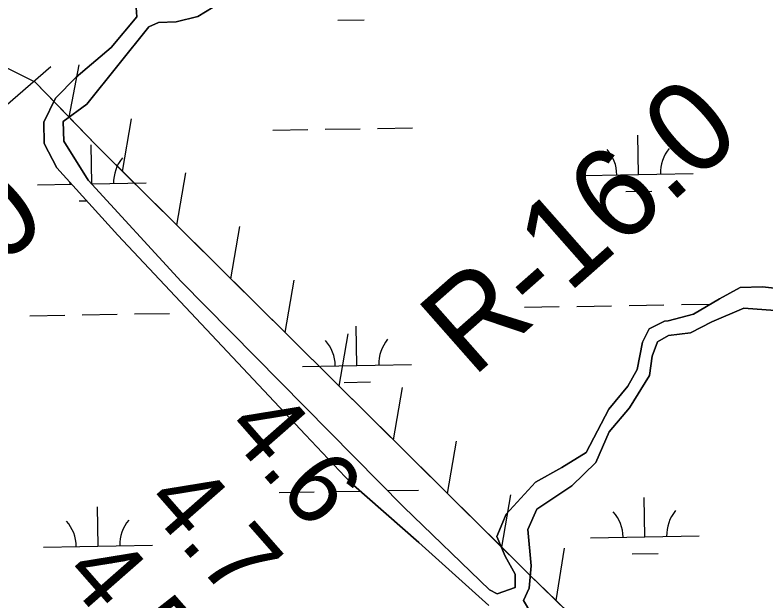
# Model space of a CAD drawing. Extents: x 3887375 to 3925618, y 296674 to 322633.
# Drawn here: x 3897469 to 3898158, y 311546 to 312084 of the extents above; entities that cross this region are included whole.
import ezdxf

# ---------------------------------------------------------------- set-up
doc = ezdxf.new("R2010")
doc.units = 0
for name, color, linetype in [('V-RIVR-EDGE', 7, 'Continuous'), ('V-RIVR-RANG', 7, 'Continuous'), ('V-RIVR-RANG-IDEN', 7, 'Continuous'), ('V-RRAP-FSHR', 7, 'Continuous'), ('V-TOPO-SHOR', 7, 'Continuous'), ('V-WETL-SWMP', 7, 'Continuous')]:
    doc.layers.add(name, color=color, linetype=linetype)

msp = doc.modelspace()

# ---------------------------------------------------------------- linework, layer by layer
at = {"layer": 'V-RIVR-EDGE'}
msp.add_spline([(3896115.81, 312736.34), (3896123.65, 312723.71), (3896129.94, 312714.39), (3896135.57, 312703.73), (3896139.52, 312690.42), (3896139.84, 312681.44), (3896138.16, 312674.8), (3896136.82, 312674.13), (3896128.53, 312683.13), (3896119.59, 312696.46), (3896111.3, 312706.79), (3896107.31, 312707.79), (3896104.98, 312706.47), (3896104.3, 312701.15), (3896107.93, 312688.84), (3896111.24, 312681.18), (3896123.51, 312667.18), (3896140.75, 312647.19), (3896160.96, 312617.21), (3896188.48, 312584.89), (3896210.04, 312563.22), (3896237.58, 312538.54), (3896253.51, 312524.87), (3896271.43, 312512.52), (3896287.7, 312501.84), (3896298.99, 312494.83), (3896306.95, 312486.83), (3896325.83, 312456.19), (3896335.76, 312438.54), (3896350.69, 312424.2), (3896373.59, 312404.53), (3896404.79, 312381.84), (3896441.98, 312359.47), (3896468.87, 312343.44), (3896491.13, 312332.41), (3896500.09, 312327.07), (3896508.39, 312318.73), (3896515.34, 312306.41), (3896528.25, 312284.43), (3896534.87, 312271.78), (3896552.8, 312258.77), (3896583.01, 312239.74), (3896613.56, 312220.04), (3896639.77, 312198.69), (3896665.32, 312175.69), (3896698.52, 312152.99), (3896718.44, 312138.98), (3896746.97, 312114.63), (3896768.21, 312094.29), (3896793.75, 312068.29), (3896812.65, 312048.29), (3896828.9, 312029.96), (3896844.47, 312006.31), (3896867.36, 311982.32), (3896895.89, 311955.97), (3896948.98, 311909.95), (3896976.52, 311885.61), (3896985.15, 311878.61), (3896997.77, 311872.92), (3897005.41, 311870.24), (3897020.03, 311862.89), (3897041.6, 311845.88), (3897061.18, 311830.87), (3897070.14, 311823.86), (3897078.77, 311813.86), (3897087.7, 311797.55), (3897092.33, 311785.56), (3897096.96, 311776.91), (3897111.21, 311756.25), (3897119.5, 311747.25), (3897129.46, 311738.58), (3897149.37, 311722.57), (3897170.94, 311704.56), (3897186.2, 311690.56), (3897201.78, 311670.24), (3897228.63, 311633.26), (3897264.74, 311581.63), (3897280, 311564.96), (3897305.21, 311539.96), (3897328.43, 311515.63), (3897360.94, 311485.95), (3897388.81, 311458.28), (3897419.34, 311434.26), (3897433.94, 311420.26), (3897454.49, 311394.6), (3897475.04, 311368.28), (3897490.64, 311354.61), (3897505.56, 311336.62), (3897515.83, 311319.63), (3897527.76, 311305.3), (3897546.67, 311288.3), (3897564.61, 311280.6), (3897578.22, 311271.26), (3897592.82, 311257.92), (3897613.06, 311238.59), (3897630.3, 311218.92), (3897644.55, 311200.6), (3897648.87, 311196.6), (3897654.85, 311195.92), (3897664.81, 311187.91), (3897681.4, 311173.9), (3897695.99, 311156.24), (3897728.16, 311123.24), (3897747.72, 311099.25), (3897753.68, 311088.26), (3897756.67, 311085.6), (3897762.65, 311082.92), (3897779.57, 311067.58), (3897798.47, 311046.92), (3897815.39, 311028.59), (3897831.98, 311014.58), (3897852.23, 310999.9), (3897867.82, 310985.56), (3897880.75, 310970.23), (3897894, 310949.25), (3897907.58, 310928.6), (3897922.16, 310908.28), (3897948.03, 310879.62), (3897967.26, 310856.62), (3897987.83, 310835.29), (3898011.71, 310813.28), (3898048.56, 310785.26), (3898064.49, 310774.25), (3898081.41, 310759.24), (3898099.65, 310738.91), (3898112.92, 310724.58), (3898123.19, 310708.59), (3898130.8, 310696.27), (3898136.77, 310688.94), (3898147.38, 310677.27), (3898159.99, 310664.27), (3898168.95, 310655.27), (3898196.47, 310623.61), (3898206.08, 310609.29), (3898214.03, 310600.63), (3898230.28, 310581.96), (3898242.21, 310565.31), (3898262.44, 310541.31), (3898281.68, 310521.32), (3898296.6, 310505.98), (3898340.41, 310470.29), (3898350.02, 310459.29), (3898356.97, 310445.31), (3898373.55, 310425.98), (3898390.14, 310409.65), (3898399.44, 310404.64), (3898413.38, 310395.29), (3898421.67, 310387.29), (3898429.97, 310378.62), (3898436.58, 310363.31), (3898463.44, 310334.65), (3898482.35, 310314.65), (3898496.61, 310298.32), (3898513.19, 310279.65), (3898535.74, 310254.66), (3898547.35, 310241.99), (3898560.27, 310224.67), (3898576.51, 310203.01), (3898592.1, 310187.68), (3898611.34, 310166.02), (3898633.55, 310138.69), (3898638.19, 310134.36), (3898642.51, 310133.02), (3898652.14, 310127.67), (3898657.79, 310123.67), (3898665.42, 310115.67), (3898676.69, 310101.68), (3898685.97, 310090.68), (3898692.61, 310085.34), (3898699.25, 310080.34), (3898707.87, 310070.01), (3898714.49, 310056.36), (3898718.44, 310043.71), (3898720.43, 310041.05), (3898727.4, 310036.37), (3898760.27, 310015.01), (3898774.22, 310006), (3898785.49, 309994.33), (3898801.4, 309973.34), (3898808.69, 309959.36), (3898822.61, 309942.36), (3898837.86, 309924.7), (3898844.83, 309916.37), (3898858.75, 309899.04), (3898871.35, 309885.38), (3898894.54, 309850.41), (3898899.85, 309846.73), (3898908.49, 309840.73), (3898917.12, 309838.05), (3898920.44, 309835.71), (3898928.06, 309822.72), (3898935.35, 309812.73), (3898943.64, 309802.73), (3898951.92, 309787.75), (3898962.85, 309772.42), (3898972.46, 309757.44), (3898979.1, 309752.43), (3898987.07, 309749.09), (3898990.72, 309745.09), (3899001.98, 309727.77), (3899013.26, 309715.44), (3899031.17, 309696.44), (3899044.76, 309680.11), (3899055.7, 309665.45), (3899064.98, 309653.79), (3899074.59, 309640.13), (3899085.54, 309630.79), (3899093.85, 309628.11), (3899099.17, 309628.1), (3899103.15, 309626.09), (3899108.12, 309616.11), (3899114.74, 309606.45), (3899123.68, 309591.13), (3899128.32, 309582.8), (3899128.31, 309580.47), (3899127.62, 309569.17), (3899127.94, 309565.84), (3899132.92, 309561.51), (3899159.78, 309529.19), (3899190.96, 309497.19), (3899204.88, 309480.52), (3899212.17, 309470.2), (3899224.78, 309457.2), (3899244.68, 309437.53), (3899252.64, 309429.86), (3899261.93, 309422.85), (3899272.56, 309415.84), (3899279.52, 309406.52), (3899287.47, 309396.19), (3899300.06, 309376.54), (3899311.33, 309362.54), (3899327.91, 309343.22), (3899342.17, 309325.56), (3899360.07, 309304.56), (3899377.31, 309282.9), (3899414.45, 309240.58), (3899433.35, 309219.58), (3899447.28, 309203.92), (3899464.53, 309184.92), (3899479.11, 309166.93), (3899493.37, 309149.94)], degree=3, dxfattribs=at)
at = {"layer": 'V-RIVR-RANG'}
msp.add_line((3897501.52, 312036.85), (3896957.19, 311565.57), dxfattribs=at)
at = {"layer": 'V-RRAP-FSHR'}
for p, q in [((3897518.09, 311990.55), (3897527.41, 312038.48)), ((3897567.25, 311940.72), (3897575.53, 311988.84)), ((3897616.95, 311891.43), (3897625.23, 311939.55)), ((3897666.65, 311842.14), (3897674.93, 311890.26)), ((3897716.36, 311792.85), (3897724.64, 311840.97)), ((3897766.06, 311743.56), (3897774.34, 311791.68)), ((3897815.76, 311694.26), (3897824.04, 311742.39)), ((3897865.46, 311644.97), (3897873.74, 311693.1)), ((3897915.16, 311595.68), (3897923.44, 311643.8)), ((3897965.07, 311546.61), (3897972.93, 311594.8))]:
    msp.add_line(p, q, dxfattribs=at)
for points in [[(3902123.51, 306879.85), (3901073.85, 308142.82), (3900480.59, 308833.04), (3899865, 309580.27), (3899505.15, 310045.27), (3899436.99, 310117.83), (3899355, 310202.28), (3899230.76, 310321.01), (3898588.27, 310939.37), (3897940.31, 311570.74), (3897542.57, 311965.2), (3897487.13, 312022.6), (3897399.6, 312065.99), (3897286.14, 312022.43), (3897238.49, 312014.24), (3897186.26, 312048.99), (3896800.61, 312251.66)], [(3897518.09, 311990.55), (3897487.13, 312022.6), (3897464.34, 312033.9), (3897401.63, 312064.98), (3897399.6, 312065.99), (3897336.36, 312041.71)], [(3897567.25, 311940.72), (3897542.57, 311965.2), (3897518.09, 311990.55)], [(3897616.95, 311891.43), (3897567.25, 311940.72)], [(3897666.65, 311842.14), (3897616.95, 311891.43)], [(3897716.36, 311792.85), (3897666.65, 311842.14)], [(3897766.06, 311743.56), (3897716.35, 311792.85)], [(3897815.76, 311694.26), (3897766.06, 311743.56)], [(3897865.46, 311644.97), (3897815.76, 311694.26)], [(3897915.16, 311595.68), (3897865.46, 311644.97)], [(3897965.07, 311546.61), (3897940.31, 311570.74), (3897915.16, 311595.68)], [(3898015.21, 311497.76), (3897965.07, 311546.61)]]:
    msp.add_lwpolyline(points, dxfattribs=at)
at = {"layer": 'V-TOPO-SHOR'}
for points in [[(3897580.25, 312082.64), (3897579.85, 312091.34), (3897572.88, 312097.8), (3897565.55, 312106.71), (3897562.24, 312117.16), (3897562.63, 312126.33), (3897566.38, 312134.73), (3897571.97, 312144.33), (3897571.44, 312153.09), (3897553.37, 312163.29), (3897542.62, 312164.06), (3897534.81, 312159.58), (3897524.87, 312141.91), (3897511.43, 312132.44), (3897492.02, 312128.26), (3897474.6, 312131.41), (3897444.89, 312146)], [(3897650.37, 312091.45), (3897636.2, 312083.03), (3897616.4, 312078.19), (3897600.33, 312077.33), (3897591.46, 312073.45)], [(3897903.39, 311542.14), (3897839.22, 311600.01), (3897776.8, 311654.65), (3897735.15, 311698.79), (3897562.92, 311882.19), (3897506.94, 311943.91), (3897495.29, 311966.35), (3897495.06, 311985.91), (3897505.56, 312008.06), (3897524.69, 312027.18), (3897556.88, 312054.35), (3897580.25, 312082.64)], [(3897591.46, 312073.45), (3897534.5, 312002.53), (3897512.69, 311986.38), (3897513.37, 311968.36), (3897535.6, 311932.81), (3897620.99, 311839.71), (3897825.24, 311632.44), (3897904.01, 311556.39), (3897910.94, 311552.8)], [(3897910.94, 311552.8), (3897927.4, 311558.68), (3897927.43, 311570.77), (3897918.38, 311587.46), (3897910.58, 311605.49), (3897919.39, 311626.1), (3897946.29, 311655.44), (3897970.22, 311668.84), (3897992.82, 311682.69), (3898013.63, 311722.41), (3898030.89, 311743.61), (3898039.41, 311758.94), (3898044.36, 311783.8), (3898050.4, 311796.27), (3898064.54, 311803.05), (3898067.91, 311803.54), (3898091.23, 311809.67), (3898115.09, 311823.67), (3898134.02, 311834.12), (3898154.55, 311834.62), (3898179.66, 311832.11)], [(3898166.27, 311812.85), (3898137.33, 311815), (3898108.18, 311802.74), (3898088.58, 311792.48)], [(3898088.58, 311792.48), (3898068.2, 311790.07), (3898058.15, 311784.25), (3898053.37, 311771.13), (3898050.84, 311753.22), (3898032.4, 311723.49), (3898013.89, 311701.68), (3898001.57, 311673.45), (3897979.69, 311652.08), (3897947.44, 311630.55), (3897939.08, 311611.93), (3897942.12, 311578.48), (3897940.24, 311557.99), (3897935.11, 311546.79), (3897957.27, 311509.8)]]:
    msp.add_lwpolyline(points, dxfattribs=at)
at = {"layer": 'V-WETL-SWMP'}
for p, q in [((3897764.93, 312079.58), (3897788.93, 312079.99)), ((3897705.25, 311978.54), (3897737.25, 311979.09)), ((3897753.24, 311979.36), (3897785.24, 311979.91)), ((3897801.24, 311980.19), (3897833.23, 311980.74)), ((3898040.84, 311937.86), (3898040.22, 311973.86)), ((3897539.01, 311929.25), (3897538.39, 311965.25)), ((3897990.85, 311937.01), (3898090.83, 311938.72)), ((3897489.01, 311928.39), (3897520.52, 311928.93)), ((3897538.86, 311929.25), (3897589, 311930.11)), ((3898029.11, 311922.23), (3898053.1, 311922.64)), ((3897527.27, 311913.62), (3897534.31, 311913.74)), ((3898080.05, 311818.45), (3898106.98, 311818.91)), ((3897936.07, 311815.98), (3897968.07, 311816.53)), ((3897984.07, 311816.8), (3898016.06, 311817.35)), ((3898032.06, 311817.62), (3898064.05, 311818.17)), ((3897482.23, 311808.19), (3897514.23, 311808.74)), ((3897530.23, 311809.01), (3897562.22, 311809.56)), ((3897578.22, 311809.83), (3897610.21, 311810.38)), ((3897782.38, 311762.59), (3897781.76, 311798.58)), ((3897732.38, 311761.73), (3897832.37, 311763.45)), ((3897770.64, 311746.96), (3897794.64, 311747.37)), ((3897710.96, 311645.91), (3897742.95, 311646.46)), ((3897758.95, 311646.74), (3897785.33, 311647.19)), ((3897810.28, 311647.62), (3897838.94, 311648.11)), ((3898046.55, 311605.24), (3898045.93, 311641.23)), ((3897544.72, 311596.62), (3897544.1, 311632.62)), ((3897996.56, 311604.38), (3898096.54, 311606.1)), ((3897494.72, 311595.77), (3897594.71, 311597.48)), ((3898034.82, 311589.6), (3898058.81, 311590.02)), ((3897532.98, 311580.99), (3897556.98, 311581.4))]:
    msp.add_line(p, q, dxfattribs=at)
for points in [[(3897444.89, 312146), (3897474.6, 312131.41), (3897492.02, 312128.26), (3897511.43, 312132.44), (3897524.87, 312141.9), (3897534.81, 312159.58), (3897542.62, 312164.06), (3897553.36, 312163.29), (3897571.44, 312153.09), (3897571.97, 312144.33), (3897566.38, 312134.73), (3897562.63, 312126.33), (3897562.24, 312117.16), (3897565.55, 312106.71), (3897572.88, 312097.81), (3897579.85, 312091.34), (3897580.25, 312082.64)], [(3897825.24, 311632.44), (3897620.99, 311839.71), (3897535.6, 311932.81), (3897513.37, 311968.36), (3897512.69, 311986.38), (3897534.5, 312002.53), (3897591.46, 312073.45), (3897600.33, 312077.33), (3897616.4, 312078.19), (3897636.2, 312083.03), (3897650.37, 312091.45)], [(3897580.25, 312082.64), (3897556.88, 312054.35), (3897524.69, 312027.18), (3897505.56, 312008.06), (3897495.06, 311985.91), (3897495.29, 311966.35), (3897506.94, 311943.91), (3897562.92, 311882.19), (3897735.15, 311698.79), (3897776.8, 311654.65), (3897839.22, 311600.01), (3897903.39, 311542.14)], [(3898179.66, 311832.11), (3898154.55, 311834.62), (3898134.02, 311834.12), (3898115.09, 311823.67), (3898091.23, 311809.67), (3898067.91, 311803.54), (3898064.54, 311803.05), (3898050.4, 311796.27), (3898044.36, 311783.8), (3898039.41, 311758.94), (3898030.89, 311743.61), (3898013.63, 311722.41), (3897992.82, 311682.69), (3897970.22, 311668.84), (3897946.29, 311655.44), (3897919.39, 311626.1), (3897910.58, 311605.49), (3897918.38, 311587.46), (3897927.43, 311570.76), (3897927.4, 311558.68), (3897910.94, 311552.8), (3897904.01, 311556.39), (3897825.24, 311632.44)], [(3897957.27, 311509.79), (3897935.11, 311546.79), (3897940.24, 311557.99), (3897942.12, 311578.48), (3897939.08, 311611.93), (3897947.44, 311630.55), (3897979.69, 311652.08), (3898001.57, 311673.45), (3898013.89, 311701.68), (3898032.4, 311723.49), (3898050.84, 311753.22), (3898053.37, 311771.13), (3898058.15, 311784.25), (3898068.2, 311790.07), (3898088.58, 311792.48), (3898108.18, 311802.74), (3898137.33, 311815)], [(3898137.33, 311815), (3898166.27, 311812.85)]]:
    msp.add_lwpolyline(points, dxfattribs=at)
for centre, start, end in [((3897985.6, 311937.39), 0.21154, 41.7552), ((3898096.07, 311939.29), 140.21154, 181.75519), ((3897594.23, 311930.67), 140.21154, 181.75519), ((3897483.76, 311928.78), 0.21154, 3.05674), ((3897727.13, 311762.12), 0.21154, 41.7552), ((3897837.6, 311764.01), 140.21154, 181.75519), ((3897991.31, 311604.76), 0.21154, 41.7552), ((3898101.78, 311606.66), 140.21154, 181.75519), ((3897489.47, 311596.15), 0.21154, 41.7552), ((3897599.94, 311598.05), 140.21154, 181.75519)]:
    msp.add_arc(centre, 35.25, start, end, dxfattribs=at)

# ---------------------------------------------------------------- texts
at = {"layer": 'V-RIVR-RANG'}
for s, p in [('4.6', (3897659.4, 311703.33)), ('4.7', (3897585.62, 311635.8)), ('4.5', (3897510.62, 311569.66))]:
    msp.add_text(s, height=67, rotation=311.26833, dxfattribs=at).set_placement(p)
at = {"layer": 'V-RIVR-RANG-IDEN'}
for s, rotation, p in [('R-16.0', 41.40853, (3897888.34, 311750.5)), ('D-110', 40.74433, (3897272.17, 311694.75))]:
    msp.add_text(s, height=83, rotation=rotation, dxfattribs=at).set_placement(p)

doc.saveas('drawing.dxf')
